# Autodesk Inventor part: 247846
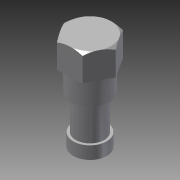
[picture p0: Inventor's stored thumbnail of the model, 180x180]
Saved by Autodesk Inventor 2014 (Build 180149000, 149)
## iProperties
Shininess: 20.0
Length Units: 11272
Angle Units: 11279
Time Units: 11290
Mass Units: 11286
Length Display Precision: 3
Angle Display Precision: 2
Company: Autodesk, Inc.
Created: 2003-01
Part Number: 247846
Material: Steel, Mild
Description: VALVE
Document SubType Name: Modeling
Designer: Autodesk, Inc.
Density: 7.86 g/cm^3
Sheet Metal Rule: Default
Mass: 238.744 g
Surface Area: 65.646 cm^2
Volume: 30.3746 cm^3
Appearance: Steel
Density: 0.0
Volumn: 0.0
Area: 0.0
PropertySet Name: Model Information
Control State: 0
Master: False
Checked Out: False
Last Check In By: JT
Last Check In Date: 2003-06-20
Title: VALVE
Author: Autodesk, Inc.
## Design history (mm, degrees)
sketch "Sketch1"
  geometry: L1 (0, 0)-(0, -47.752); L2 (0, -47.752)-(11.113, -47.752); L3 (11.113, -47.752)-(11.113, -39.294); L4 (11.113, -39.294)-(9.525, -39.294); L5 (12.7, -3.962)-(13.081, -3.962); L6 (13.081, -3.962)-(13.081, 0); L7 (13.081, 0)-(16.51, 0); L8 (16.51, 0)-(16.51, 15.875); L9 (16.51, 15.875)-(14.224, 17.526); L10 (14.224, 17.526)-(0, 17.526); L11 (0, 17.526)-(0, 0); L12 (12.7, -3.962)-(12.7, -15.875); L13 (12.7, -15.875)-(9.525, -15.875); L14 (9.525, -15.875)-(9.525, -39.294)
  constraints: 28 end point, 8 parallel, 3 perpendicular, 1 collinear, 1 horizontal alignment, 1 vertical
  dimensions: "d3" = 17.526 distance from line of L10 L1.start; "d4" = 47.752 distance from line of L2 L1.start; "d5" = 22.225 diameter of L3 L1; "d6" = 39.2938 distance from line of L4 L1.start; "d7" = 26.162 diameter of L6 L1; "d9" = 3.9624 distance from line of L5 L1.start; "d10" = 19.05 diameter of L14 L1; "d11" = 25.4 diameter of L12 L1; "d12" = 15.875 distance from line of L13 L1.start; "d13" = 33.02 diameter of L8 L11; "d14" = 28.448 diameter of L9.end L11; "d15" = 15.875 distance of L7.end L8.end
revolve "Revolution1" sketch "Sketch1" stored, may be unused: angle "d16" = 90 deg
sketch "Sketch2"
  geometry: L1 (-7.551, -14.586)-(-16.407, -0.754); L2 (-16.407, -0.754)-(-8.856, 13.832); L3 (-8.856, 13.832)-(7.551, 14.586); L4 (7.551, 14.586)-(16.407, 0.754); L5 (16.407, 0.754)-(8.856, -13.832); L6 (8.856, -13.832)-(-7.551, -14.586); C1 r 14.224 at (0, 0) reference; C2 r 26.553 at (0, 0); 1 further point
  constraints: 12 end point, 2 coincident, 1 centre point, 11 other
  dimensions: "d17" = 28.448 distance between parallel lines of L6 L3
extrude "Extrusion2" cut sketch "Sketch2" distance "d18" = 25.4; taper "d19" = 0 deg
body "Solid1"
other parameters: "Thickness" = 6.35, "BendRadius" = 6.35, "BendReliefWidth" = 6.35 (= Thickness), "BendReliefDepth" = 3.175 (= 0.5 x Thickness), "CornerReliefSize" = 25.4 (= 4 x Thickness), "SeamGap" = 0.00508, "MinimumRemnant" = 12.7 (= 2 x Thickness), "TransitionRadius" = 6.35 (= BendRadius), "JacobiRadiusSize" = 6.35 (= Thickness), "GapSize" = 6.35 (= Thickness)
